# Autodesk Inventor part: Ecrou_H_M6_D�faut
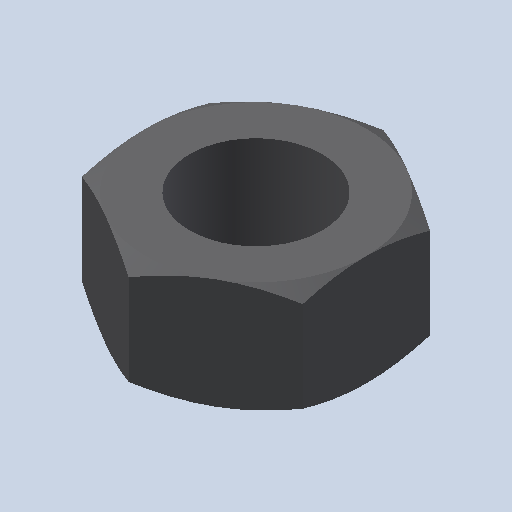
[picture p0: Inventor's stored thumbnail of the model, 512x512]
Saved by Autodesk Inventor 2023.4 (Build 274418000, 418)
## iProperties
Created: 2011-01
Part Number: Ecrou_H_M6_D�faut
Document SubType Name: Modeling
Designer: eric
Density: 1 g/cm^3
Mass: 0.289469 g
Surface Area: 3.75991 cm^2
Volume: 0.289469 cm^3
Material: Générique
Appearance: Blue
Author: eric
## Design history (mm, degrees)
feature "Base1"
node "Corps solides"
node "Corps surfaciques"
node "Solide1"
